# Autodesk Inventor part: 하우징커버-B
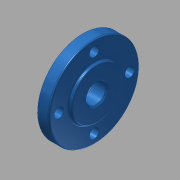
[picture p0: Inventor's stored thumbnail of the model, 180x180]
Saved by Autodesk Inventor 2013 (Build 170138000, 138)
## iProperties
Created: 2018-01
Part Number: 하우징커버-B
Material: 알루미늄 6061
Document SubType Name: Modeling
Designer: mduedu
Density: 2.71 g/cm^3
Mass: 8.4704 g
Surface Area: 21.4635 cm^2
Volume: 3.12561 cm^3
Author: mduedu
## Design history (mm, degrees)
sketch "스케치1"
  geometry: C1 r 16 at (0, 0); 1 further point
  constraints: 1 centre point, 1 coincident
  dimensions: "d0" = 32 diameter of C1
extrude "돌출1" new body sketch "스케치1" distance "d1" = 4; taper "d2" = 0 deg
sketch "스케치2"
  geometry: C1 r 9 at (0, 0); 1 further point
  constraints: 1 centre point, 1 coincident
  dimensions: "d3" = 18 diameter of C1
extrude "돌출2" join sketch "스케치2" distance "d4" = 1; taper "d5" = 0 deg
fillet "모깎기1" dims "d6" = 0.5
fillet "모깎기2" dims "d7" = 0.5
hole "구멍1" diameter "d10" = 7; stored, may be unused: countersink angle "d14" = 90 deg, drill point angle "d16" = 118 deg; dims "d8" = 10, "d9" = 10, "d11" = 6, "d12" = 4, "d13" = 2, "d15" = 8
chamfer "모따기1" distance "d17" = 0.5; stored, may be unused: second distance "d18" = 2, angle "d19" = 45 deg
sketch "스케치3" dims "d21" = 25
  geometry: 6 further points
  constraints: 2 vertical alignment, 1 coincident, 7 other
  dimensions: "d24" = 360 deg dimension on point (0, 0) point (0, 12.5) (derived)
sketch "스케치4"
  geometry: 4 further points
  constraints: 4 other
hole "구멍2" sketch "스케치4" at (-12.5, 0), (0, -12.5), (12.5, 0), (0, 12.5) diameter "d26" = 3.4; stored, may be unused: countersink angle "d30" = 90 deg, drill point angle "d32" = 0 deg; dims "d27" = 6, "d28" = 4, "d29" = 2, "d31" = 8
node "솔리드1"
